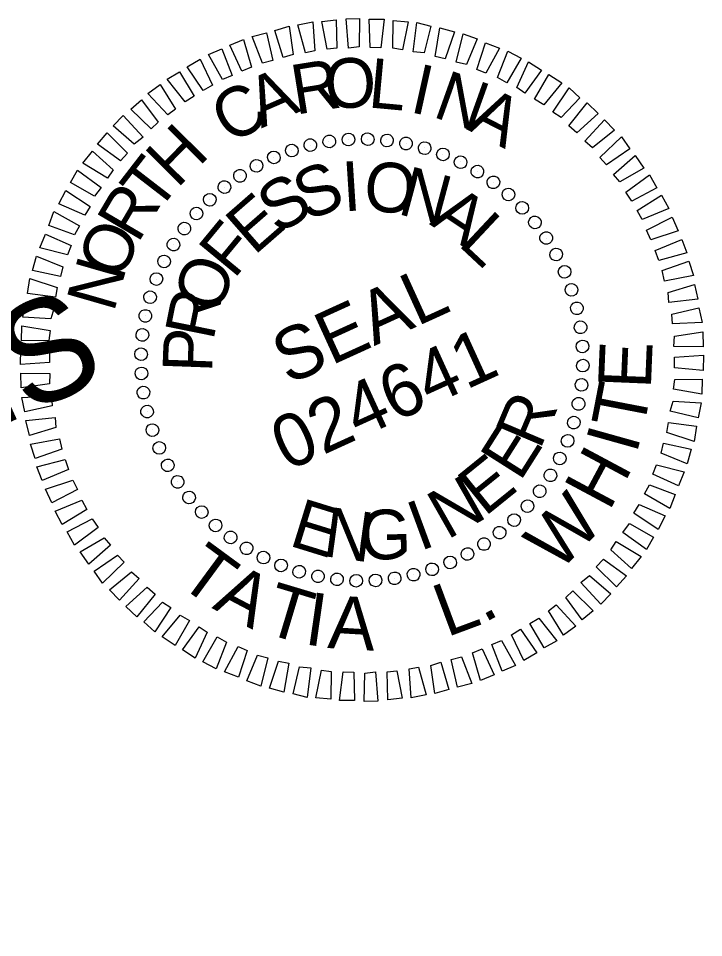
# Model space of a CAD drawing. Extents: x 2247910 to 2249896, y 662531 to 664300.
# Drawn here: x 2249665.3 to 2249743.1, y 664153.9 to 664258.3 of the extents above; entities that cross this region are included whole.
import ezdxf

# ---------------------------------------------------------------- set-up
doc = ezdxf.new("R2010")
doc.units = 0
doc.layers.add('Sheet Professional Seal CELL', color=7, linetype='Continuous')
doc.layers.add('Sheet Sticker Incomplete CELL', color=7, linetype='Continuous')

msp = doc.modelspace()

# ---------------------------------------------------------------- linework, layer by layer
at = {"layer": 'Sheet Professional Seal CELL'}
for p, q in [((2249702.77, 664244.61), (2249702.77, 664244.61)), ((2249704.96, 664244.62), (2249704.96, 664244.62)), ((2249707.15, 664244.52), (2249707.15, 664244.52)), ((2249698.47, 664243.92), (2249698.47, 664243.92)), ((2249700.57, 664244.38), (2249700.57, 664244.38)), ((2249709.31, 664244.13), (2249709.31, 664244.13)), ((2249711.46, 664243.63), (2249711.46, 664243.63)), ((2249694.31, 664242.57), (2249694.31, 664242.57)), ((2249696.37, 664243.34), (2249696.37, 664243.34)), ((2249713.5, 664242.91), (2249713.5, 664242.91)), ((2249692.33, 664241.61), (2249692.33, 664241.61)), ((2249715.54, 664242.03), (2249715.54, 664242.03)), ((2249690.49, 664240.44), (2249690.49, 664240.44)), ((2249717.41, 664240.96), (2249717.41, 664240.96)), ((2249719.24, 664239.7), (2249719.24, 664239.7)), ((2249688.66, 664239.17), (2249688.66, 664239.17)), ((2249720.96, 664238.34), (2249720.96, 664238.34)), ((2249687, 664237.75), (2249687, 664237.75)), ((2249685.51, 664236.19), (2249685.51, 664236.19)), ((2249722.52, 664236.86), (2249722.52, 664236.86)), ((2249723.94, 664235.19), (2249723.94, 664235.19)), ((2249684.15, 664234.47), (2249684.15, 664234.47)), ((2249725.21, 664233.36), (2249725.21, 664233.36)), ((2249682.9, 664232.64), (2249682.9, 664232.64)), ((2249726.38, 664231.53), (2249726.38, 664231.53)), ((2249681.82, 664230.77), (2249681.82, 664230.77)), ((2249727.34, 664229.55), (2249727.34, 664229.55)), ((2249680.95, 664228.73), (2249680.95, 664228.73)), ((2249728.11, 664227.48), (2249728.11, 664227.48)), ((2249680.22, 664226.69), (2249680.22, 664226.69)), ((2249728.69, 664225.38), (2249728.69, 664225.38)), ((2249679.72, 664224.54), (2249679.72, 664224.54)), ((2249729.15, 664223.28), (2249729.15, 664223.28)), ((2249679.33, 664222.38), (2249679.33, 664222.38)), ((2249729.38, 664221.08), (2249729.38, 664221.08)), ((2249679.23, 664220.19), (2249679.23, 664220.19)), ((2249704.31, 664219.54), (2249704.31, 664219.54)), ((2249729.39, 664218.89), (2249729.39, 664218.89)), ((2249679.24, 664218), (2249679.24, 664218)), ((2249729.29, 664216.7), (2249729.29, 664216.7)), ((2249679.48, 664215.8), (2249679.48, 664215.8)), ((2249728.9, 664214.54), (2249728.9, 664214.54)), ((2249679.94, 664213.7), (2249679.94, 664213.7)), ((2249728.4, 664212.39), (2249728.4, 664212.39)), ((2249680.51, 664211.6), (2249680.51, 664211.6)), ((2249727.68, 664210.36), (2249727.68, 664210.36)), ((2249681.29, 664209.54), (2249681.29, 664209.54)), ((2249726.8, 664208.31), (2249726.8, 664208.31)), ((2249682.25, 664207.56), (2249682.25, 664207.56)), ((2249725.73, 664206.45), (2249725.73, 664206.45)), ((2249683.41, 664205.72), (2249683.41, 664205.72)), ((2249684.69, 664203.89), (2249684.69, 664203.89)), ((2249724.47, 664204.61), (2249724.47, 664204.61)), ((2249723.11, 664202.89), (2249723.11, 664202.89)), ((2249686.1, 664202.23), (2249686.1, 664202.23)), ((2249687.66, 664200.74), (2249687.66, 664200.74)), ((2249721.63, 664201.33), (2249721.63, 664201.33)), ((2249719.96, 664199.92), (2249719.96, 664199.92)), ((2249689.38, 664199.38), (2249689.38, 664199.38)), ((2249718.13, 664198.64), (2249718.13, 664198.64)), ((2249691.22, 664198.13), (2249691.22, 664198.13)), ((2249693.08, 664197.05), (2249693.08, 664197.05)), ((2249714.32, 664196.52), (2249714.32, 664196.52)), ((2249716.3, 664197.48), (2249716.3, 664197.48)), ((2249695.13, 664196.18), (2249695.13, 664196.18)), ((2249697.16, 664195.45), (2249697.16, 664195.45)), ((2249712.25, 664195.74), (2249712.25, 664195.74)), ((2249699.31, 664194.95), (2249699.31, 664194.95)), ((2249701.47, 664194.56), (2249701.47, 664194.56)), ((2249703.66, 664194.46), (2249703.66, 664194.46)), ((2249705.85, 664194.47), (2249705.85, 664194.47)), ((2249708.05, 664194.71), (2249708.05, 664194.71)), ((2249710.15, 664195.17), (2249710.15, 664195.17))]:
    msp.add_line(p, q, dxfattribs=at)
for points in [[(2249700.36, 664254.83), (2249699.76, 664257.97), (2249701.38, 664258.15), (2249701.46, 664254.95)], [(2249702.78, 664254.95), (2249702.52, 664258.29), (2249704.05, 664258.33), (2249703.98, 664255.11)], [(2249705.23, 664255.02), (2249705.14, 664258.22), (2249706.84, 664258.23), (2249706.45, 664254.97)], [(2249707.8, 664254.93), (2249707.84, 664258.08), (2249709.56, 664257.93), (2249708.91, 664254.77)], [(2249695.36, 664253.87), (2249694.44, 664256.97), (2249696.05, 664257.43), (2249696.52, 664254.23)], [(2249697.91, 664254.43), (2249697.02, 664257.59), (2249698.73, 664257.94), (2249698.97, 664254.64)], [(2249710.13, 664254.51), (2249710.52, 664257.87), (2249712.14, 664257.46), (2249711.38, 664254.42)], [(2249712.62, 664253.99), (2249713.16, 664257.26), (2249714.8, 664256.8), (2249713.77, 664253.75)], [(2249693.01, 664253.24), (2249691.85, 664256.28), (2249693.47, 664256.69), (2249694.19, 664253.56)], [(2249714.99, 664253.37), (2249715.78, 664256.59), (2249717.37, 664255.99), (2249716.16, 664253.08)], [(2249690.68, 664252.34), (2249689.33, 664255.3), (2249690.85, 664255.94), (2249691.79, 664252.79)], [(2249717.35, 664252.52), (2249718.33, 664255.56), (2249719.92, 664254.96), (2249718.37, 664252.11)], [(2249688.47, 664251.39), (2249686.89, 664254.24), (2249688.42, 664254.88), (2249689.58, 664251.84)], [(2249719.69, 664251.61), (2249720.85, 664254.61), (2249722.37, 664253.82), (2249720.74, 664250.99)], [(2249686.3, 664250.13), (2249684.47, 664252.81), (2249685.94, 664253.7), (2249687.33, 664250.76)], [(2249721.87, 664250.46), (2249723.22, 664253.39), (2249724.69, 664252.46), (2249722.81, 664249.85)], [(2249684.24, 664248.86), (2249682.19, 664251.44), (2249683.62, 664252.26), (2249685.27, 664249.49)], [(2249723.9, 664249.14), (2249725.52, 664251.96), (2249727.01, 664250.99), (2249724.95, 664248.52)], [(2249682.29, 664247.36), (2249680.02, 664249.79), (2249681.42, 664250.81), (2249683.14, 664248.02)], [(2249725.99, 664247.67), (2249727.82, 664250.43), (2249729.05, 664249.29), (2249726.93, 664247.06)], [(2249680.37, 664245.77), (2249678.08, 664248.03), (2249679.3, 664249.08), (2249681.18, 664246.53)], [(2249727.8, 664246.13), (2249729.86, 664248.72), (2249731.11, 664247.53), (2249728.71, 664245.34)], [(2249678.47, 664244.03), (2249676.09, 664246.13), (2249677.2, 664247.3), (2249679.49, 664244.82)], [(2249729.59, 664244.37), (2249731.83, 664246.82), (2249732.97, 664245.63), (2249730.48, 664243.62)], [(2249676.91, 664242.16), (2249674.29, 664244.04), (2249675.41, 664245.32), (2249677.72, 664243.03)], [(2249731.31, 664242.52), (2249733.75, 664244.89), (2249734.71, 664243.51), (2249732.07, 664241.7)], [(2249675.45, 664240.18), (2249672.65, 664241.87), (2249673.72, 664243.24), (2249676.06, 664241.12)], [(2249732.86, 664240.58), (2249735.33, 664242.75), (2249736.31, 664241.33), (2249733.56, 664239.75)], [(2249673.97, 664238.13), (2249671.23, 664239.68), (2249672.01, 664241.08), (2249674.72, 664239.13)], [(2249734.26, 664238.58), (2249736.93, 664240.57), (2249737.77, 664239.08), (2249734.94, 664237.57)], [(2249672.86, 664235.97), (2249669.91, 664237.27), (2249670.7, 664238.78), (2249673.45, 664236.96)], [(2249735.53, 664236.52), (2249738.32, 664238.24), (2249739.12, 664236.73), (2249736.12, 664235.47)], [(2249671.68, 664233.73), (2249668.77, 664234.82), (2249669.36, 664236.41), (2249672.26, 664234.76)], [(2249736.61, 664234.27), (2249739.51, 664235.76), (2249740.21, 664234.21), (2249737.11, 664233.18)], [(2249670.91, 664231.46), (2249667.74, 664232.26), (2249668.4, 664233.83), (2249671.3, 664232.52)], [(2249737.6, 664231.97), (2249740.6, 664233.23), (2249741.2, 664231.69), (2249738.01, 664230.84)], [(2249670.1, 664229), (2249666.93, 664229.7), (2249667.39, 664231.34), (2249670.37, 664230.11)], [(2249738.37, 664229.69), (2249741.41, 664230.74), (2249741.93, 664229.11), (2249738.64, 664228.49)], [(2249669.53, 664226.65), (2249666.37, 664227.08), (2249666.63, 664228.79), (2249669.72, 664227.78)], [(2249739.07, 664227.2), (2249742.05, 664228.12), (2249742.44, 664226.43), (2249739.14, 664226.08)], [(2249668.99, 664224.21), (2249665.82, 664224.41), (2249666.15, 664226.1), (2249669.35, 664225.36)], [(2249739.47, 664224.75), (2249742.56, 664225.44), (2249742.93, 664223.8), (2249739.54, 664223.63)], [(2249668.79, 664221.75), (2249665.68, 664221.71), (2249665.72, 664223.43), (2249668.94, 664222.87)], [(2249739.78, 664222.25), (2249742.98, 664222.72), (2249743.03, 664221.04), (2249739.72, 664221.07)], [(2249668.84, 664219.25), (2249665.54, 664219.01), (2249665.58, 664220.73), (2249668.84, 664220.46)], [(2249739.79, 664219.84), (2249743.08, 664220.08), (2249743.05, 664218.35), (2249739.79, 664218.63)], [(2249668.84, 664216.83), (2249665.65, 664216.36), (2249665.59, 664218.04), (2249668.9, 664218.01)], [(2249739.83, 664217.33), (2249742.94, 664217.37), (2249742.9, 664215.65), (2249739.68, 664216.22)], [(2249669.15, 664214.34), (2249666.06, 664213.64), (2249665.7, 664215.29), (2249669.08, 664215.46)], [(2249739.63, 664214.87), (2249742.8, 664214.67), (2249742.47, 664212.98), (2249739.28, 664213.72)], [(2249669.56, 664211.88), (2249666.57, 664210.96), (2249666.18, 664212.65), (2249669.49, 664213)], [(2249739.1, 664212.43), (2249742.26, 664212.01), (2249742, 664210.29), (2249738.9, 664211.3)], [(2249670.25, 664209.4), (2249667.22, 664208.34), (2249666.69, 664209.97), (2249669.98, 664210.59)], [(2249738.52, 664210.08), (2249741.69, 664209.39), (2249741.23, 664207.75), (2249738.26, 664208.97)], [(2249671.02, 664207.11), (2249668.02, 664205.85), (2249667.43, 664207.39), (2249670.61, 664208.24)], [(2249737.72, 664207.63), (2249740.89, 664206.82), (2249740.23, 664205.25), (2249737.32, 664206.57)], [(2249672.01, 664204.81), (2249669.12, 664203.33), (2249668.41, 664204.88), (2249671.51, 664205.9)], [(2249736.94, 664205.35), (2249739.86, 664204.26), (2249739.26, 664202.67), (2249736.37, 664204.32)], [(2249673.09, 664202.56), (2249670.3, 664200.85), (2249669.51, 664202.35), (2249672.51, 664203.61)], [(2249735.76, 664203.11), (2249738.72, 664201.82), (2249737.92, 664200.3), (2249735.17, 664202.12)], [(2249674.36, 664200.5), (2249671.7, 664198.51), (2249670.85, 664200), (2249673.68, 664201.51)], [(2249734.66, 664200.96), (2249737.4, 664199.4), (2249736.61, 664198), (2249733.91, 664199.95)], [(2249675.77, 664198.5), (2249673.3, 664196.33), (2249672.32, 664197.75), (2249675.06, 664199.33)], [(2249733.17, 664198.91), (2249735.98, 664197.22), (2249734.9, 664195.85), (2249732.56, 664197.97)], [(2249677.31, 664196.57), (2249674.88, 664194.19), (2249673.92, 664195.57), (2249676.56, 664197.38)], [(2249731.72, 664196.92), (2249734.33, 664195.04), (2249733.21, 664193.76), (2249730.9, 664196.06)], [(2249679.03, 664194.72), (2249676.8, 664192.27), (2249675.65, 664193.45), (2249678.14, 664195.46)], [(2249730.15, 664195.05), (2249732.54, 664192.96), (2249731.42, 664191.79), (2249729.14, 664194.26)], [(2249680.83, 664192.95), (2249678.77, 664190.36), (2249677.51, 664191.55), (2249679.92, 664193.75)], [(2249728.25, 664193.31), (2249730.54, 664191.06), (2249729.32, 664190.01), (2249727.44, 664192.56)], [(2249682.63, 664191.41), (2249680.81, 664188.66), (2249679.57, 664189.8), (2249681.69, 664192.03)], [(2249726.34, 664191.72), (2249728.6, 664189.29), (2249727.2, 664188.27), (2249725.49, 664191.06)], [(2249684.72, 664189.95), (2249683.1, 664187.12), (2249681.62, 664188.09), (2249683.67, 664190.57)], [(2249724.38, 664190.23), (2249726.44, 664187.65), (2249725, 664186.83), (2249723.35, 664189.59)], [(2249686.76, 664188.62), (2249685.4, 664185.69), (2249683.93, 664186.62), (2249685.82, 664189.24)], [(2249722.32, 664188.96), (2249724.15, 664186.27), (2249722.69, 664185.39), (2249721.29, 664188.32)], [(2249688.93, 664187.47), (2249687.77, 664184.47), (2249686.26, 664185.26), (2249687.88, 664188.09)], [(2249720.15, 664187.69), (2249721.73, 664184.84), (2249720.21, 664184.2), (2249719.04, 664187.24)], [(2249691.27, 664186.56), (2249690.29, 664183.53), (2249688.7, 664184.12), (2249690.26, 664186.98)], [(2249717.95, 664186.74), (2249719.3, 664183.79), (2249717.77, 664183.15), (2249716.84, 664186.29)], [(2249693.63, 664185.71), (2249692.85, 664182.5), (2249691.26, 664183.09), (2249692.46, 664186)], [(2249696.01, 664185.09), (2249695.46, 664181.82), (2249693.83, 664182.28), (2249694.85, 664185.33)], [(2249713.26, 664185.21), (2249714.18, 664182.11), (2249712.58, 664181.66), (2249712.11, 664184.85)], [(2249715.61, 664185.84), (2249716.78, 664182.8), (2249715.15, 664182.39), (2249714.44, 664185.53)], [(2249698.49, 664184.58), (2249698.11, 664181.21), (2249696.49, 664181.63), (2249697.24, 664184.67)], [(2249700.83, 664184.16), (2249700.78, 664181), (2249699.07, 664181.16), (2249699.72, 664184.31)], [(2249703.4, 664184.07), (2249703.48, 664180.86), (2249701.78, 664180.86), (2249702.17, 664184.11)], [(2249705.84, 664184.13), (2249706.1, 664180.79), (2249704.58, 664180.76), (2249704.65, 664183.98)], [(2249708.26, 664184.25), (2249708.86, 664181.12), (2249707.25, 664180.93), (2249707.16, 664184.13)], [(2249710.71, 664184.65), (2249711.61, 664181.49), (2249709.89, 664181.15), (2249709.65, 664184.45)]]:
    msp.add_lwpolyline(points, close=True, dxfattribs=at)
for centre, major_axis in [((2249698.45, 664243.93), (-0.168, 0.7)), ((2249700.6, 664244.35), (-0.107, 0.712)), ((2249702.78, 664244.57), (-0.044, 0.719)), ((2249704.96, 664244.61), (0.019, 0.72)), ((2249707.15, 664244.46), (0.081, 0.715)), ((2249709.31, 664244.12), (0.143, 0.706)), ((2249696.35, 664243.32), (-0.229, 0.683)), ((2249711.43, 664243.59), (0.204, 0.69)), ((2249713.5, 664242.88), (0.264, 0.67)), ((2249692.34, 664241.58), (-0.344, 0.633)), ((2249694.31, 664242.54), (-0.287, 0.66)), ((2249715.5, 664241.99), (0.321, 0.644)), ((2249717.41, 664240.93), (0.376, 0.614)), ((2249690.46, 664240.45), (-0.398, 0.6)), ((2249719.23, 664239.71), (0.428, 0.579)), ((2249688.7, 664239.17), (-0.448, 0.563)), ((2249687.04, 664237.73), (-0.496, 0.522)), ((2249720.93, 664238.33), (0.477, 0.539)), ((2249722.5, 664236.81), (0.522, 0.496)), ((2249685.52, 664236.16), (-0.539, 0.477)), ((2249684.15, 664234.46), (-0.579, 0.428)), ((2249723.94, 664235.16), (0.563, 0.448)), ((2249725.22, 664233.39), (0.6, 0.398)), ((2249682.92, 664232.64), (-0.614, 0.376)), ((2249726.35, 664231.51), (0.633, 0.344)), ((2249681.86, 664230.73), (-0.644, 0.321)), ((2249727.31, 664229.55), (0.66, 0.287)), ((2249680.98, 664228.73), (-0.67, 0.264)), ((2249728.09, 664227.5), (0.683, 0.229)), ((2249680.26, 664226.66), (-0.69, 0.204)), ((2249728.7, 664225.4), (0.7, 0.168)), ((2249679.73, 664224.54), (-0.706, 0.143)), ((2249729.12, 664223.25), (0.712, 0.107)), ((2249679.39, 664222.38), (-0.715, 0.081)), ((2249729.34, 664221.08), (0.719, 0.044)), ((2249679.24, 664220.19), (-0.72, 0.019)), ((2249729.38, 664218.89), (0.72, -0.019)), ((2249679.28, 664218.01), (-0.719, -0.044)), ((2249729.23, 664216.71), (0.715, -0.081)), ((2249679.51, 664215.83), (-0.712, -0.107)), ((2249728.89, 664214.55), (0.706, -0.143)), ((2249679.93, 664213.68), (-0.7, -0.168)), ((2249728.36, 664212.42), (0.69, -0.204)), ((2249680.53, 664211.58), (-0.683, -0.229)), ((2249727.65, 664210.35), (0.67, -0.264)), ((2249681.31, 664209.54), (-0.66, -0.287)), ((2249726.76, 664208.36), (0.644, -0.321)), ((2249682.27, 664207.57), (-0.633, -0.344)), ((2249725.7, 664206.44), (0.614, -0.376)), ((2249683.4, 664205.69), (-0.6, -0.398)), ((2249724.48, 664204.63), (0.579, -0.428)), ((2249684.69, 664203.92), (-0.563, -0.448)), ((2249686.12, 664202.27), (-0.522, -0.496)), ((2249723.1, 664202.93), (0.539, -0.477)), ((2249721.58, 664201.35), (0.496, -0.522)), ((2249687.7, 664200.75), (-0.477, -0.539)), ((2249719.93, 664199.92), (0.448, -0.563)), ((2249689.4, 664199.38), (-0.428, -0.579)), ((2249691.21, 664198.15), (-0.376, -0.614)), ((2249718.16, 664198.63), (0.398, -0.6)), ((2249693.13, 664197.09), (-0.321, -0.644)), ((2249716.28, 664197.5), (0.344, -0.633)), ((2249695.13, 664196.2), (-0.264, -0.67)), ((2249712.27, 664195.76), (0.229, -0.683)), ((2249714.32, 664196.54), (0.287, -0.66)), ((2249697.19, 664195.49), (-0.204, -0.69)), ((2249699.32, 664194.96), (-0.143, -0.706)), ((2249708.02, 664194.74), (0.107, -0.712)), ((2249710.17, 664195.16), (0.168, -0.7)), ((2249701.48, 664194.62), (-0.081, -0.715)), ((2249703.66, 664194.47), (-0.019, -0.72)), ((2249705.85, 664194.51), (0.044, -0.719))]:
    msp.add_ellipse(centre, major_axis=major_axis, ratio=0.999708, dxfattribs=at)

# ---------------------------------------------------------------- texts
for s, height, rotation, p in [('O', 5.64, 1.9334, (2249700.14, 664248.08)), ('R', 5.64, 9.1334, (2249696.78, 664247.38)), ('L', 5.64, 354.7331, (2249704.91, 664248.23)), ('I', 5.64, 347.5324, (2249709.6, 664247.72)), ('A', 5.64, 23.5326, (2249692.88, 664245.82)), ('N', 5.64, 340.3312, (2249712.19, 664247.21)), ('C', 5.64, 30.7321, (2249689.41, 664243.91)), ('A', 5.64, 333.1294, (2249716.1, 664245.75)), ('H', 5.64, 45.1317, (2249683.33, 664238.93)), ('T', 5.64, 52.332, (2249681.05, 664236.08)), ('S', 5.64, 22.4127, (2249698.03, 664235.25)), ('I', 5.64, 3.7019, (2249702.23, 664236.4)), ('O', 5.64, 354.3457, (2249704.34, 664236.59)), ('N', 5.64, 344.9889, (2249708.22, 664236.16)), ('S', 5.64, 31.7679, (2249694.77, 664233.71)), ('R', 5.64, 59.5328, (2249678.87, 664232.67)), ('E', 5.64, 41.1233, (2249692.07, 664231.32)), ('A', 5.64, 326.2725, (2249711.89, 664234.98)), ('L', 5.64, 316.9131, (2249715.1, 664232.65)), ('F', 5.64, 50.4793, (2249689.78, 664228.63)), ('O', 5.64, 66.734, (2249677.02, 664228.42)), ('N', 5.64, 73.9358, (2249676.13, 664224.83)), ('O', 5.64, 69.1935, (2249688, 664224.58)), ('SEAL', 5.998, 24.5123, (2249695.95, 664216.66)), ('R', 5.64, 78.5519, (2249687.43, 664221.62)), ('P', 5.64, 87.9112, (2249687.3, 664218.05)), ('024641', 5.998, 24.5123, (2249695.83, 664206.87)), ('E', 6, 87.6312, (2249737.09, 664216.18)), ('T', 6, 79.1093, (2249736.23, 664211.36)), ('R', 5.64, 66.9937, (2249724.51, 664209.24)), ('E', 5.64, 57.6364, (2249722.25, 664205.63)), ('I', 6, 74.3449, (2249735.44, 664208.74)), ('H', 6, 61.8333, (2249732.36, 664202.25)), ('E', 5.64, 38.924, (2249718.24, 664201.66)), ('N', 5.64, 29.5687, (2249713.98, 664199.06)), ('W', 6, 46.126, (2249726.64, 664195.3)), ('E', 5.64, 342.7892, (2249695.88, 664198.5)), ('N', 5.64, 352.1462, (2249699.73, 664197.29)), ('I', 5.64, 20.2135, (2249710.87, 664197.8)), ('G', 5.64, 1.5025, (2249704.12, 664196.82)), ('T', 6, 323.6774, (2249683.22, 664194.23)), ('A', 6, 332.1992, (2249687.2, 664191.38)), ('T', 6, 343.2776, (2249692.93, 664188.62)), ('L', 6, 20.425, (2249713.92, 664188.02)), ('I', 6, 351.7994, (2249697.64, 664187.27)), ('A', 6, 356.5639, (2249700.34, 664186.83)), ('.', 6, 28.2883, (2249718.14, 664189.63))]:
    msp.add_text(s, height=height, rotation=rotation, dxfattribs=at).set_placement(p)
at = {"layer": 'Sheet Sticker Incomplete CELL'}
msp.add_text('INCOMPLETE PLANS', height=11.52, rotation=24.4979, dxfattribs=at).set_placement((2249534.63, 664153.35))

doc.saveas('drawing.dxf')
